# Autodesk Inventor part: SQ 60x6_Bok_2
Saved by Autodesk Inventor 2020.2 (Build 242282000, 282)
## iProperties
Created: 2006-08
Part Number: SQ 60x6_Bok_2
Material: Ogólny
Document SubType Name: Modeling
Designer: F.Stasiak
Manufacturer: Standard
Standards Organization: Custom
Stock Number: DIN EN 10210-2 SQ 60x6
Density: 1 g/cm^3
Appearance: Domyślna
Manager: www.cadconsulting.pl
Company: Fabian Stasiak CAD Consulting
G_L: 500,0 mm
G_W: 60,000 mm
G_H: 60,000 mm
AFG_Item: 60 x 60 x 6
Author: F.Stasiak
Subject: Zbiór ćwiczeń. Autodesk Inventor 2020. Kurs podstawowy
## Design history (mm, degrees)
sketch "AFG_Detailed"
  geometry: L1 (48, -6)-(12, -6); L2 (6, -12)-(6, -48); L3 (12, -54)-(48, -54); L4 (54, -48)-(54, -12); L5 (48, 0)-(12, 0); L6 (0, -12)-(0, -48); L7 (12, -60)-(48, -60); L8 (60, -48)-(60, -12); A1 r 6 centre (48, -12) between (54, -12) and (48, -6); A2 r 12 centre (48, -12) between (60, -12) and (48, 0); A3 r 6 centre (48, -48) between (48, -54) and (54, -48); A4 r 12 centre (48, -48) between (48, -60) and (60, -48); A5 r 12 centre (12, -48) between (0, -48) and (12, -60); A6 r 6 centre (12, -48) between (6, -48) and (12, -54); A7 r 6 centre (12, -12) between (12, -6) and (6, -12); A8 r 12 centre (12, -12) between (12, 0) and (0, -12); 4 further points
  constraints: 16 end point, 16 point on circle, 16 tangent, 8 centre point, 6 point on line, 4 parallel, 2 perpendicular, 1 vertical
  dimensions: "d15" = 60 distance of point (0, -60) point (60, -60) (= GEO_B); "d16" = 6 distance between parallel lines of L7 L3 (= GEO_S); "d17" = 6 distance between parallel lines of L8 L4 (= GEO_S); "d18" = 6 distance between parallel lines of L5 L1 (= GEO_S); "d19" = 6 distance between parallel lines of L6 L2 (= GEO_S); "d20" = 30 distance from line of point (30, -30) L7 (= 0.5 x GEO_H); "d30" = 6 radius of A1 (= GEO_R1 - GEO_S); "GEO_R1" = 12 radius of A2; "d32" = 6 radius of A3 (= GEO_R1 - GEO_S); "d33" = 12 radius of A4 (= GEO_R1); "d34" = 12 radius of A5 (= GEO_R1); "d35" = 6 radius of A6 (= GEO_R1 - GEO_S); "d36" = 6 radius of A7 (= GEO_R1 - GEO_S); "d37" = 12 radius of A8 (= GEO_R1); "d38" = 30 distance from line of L6 point (30, -30) (= 0.5 x GEO_B); "d39" = 60 distance between parallel lines of L7 L5 (= GEO_H)
sketch "AFG_Medium"
  geometry: L1 (54, -6)-(6, -6); L2 (6, -6)-(6, -54); L3 (6, -54)-(54, -54); L4 (54, -54)-(54, -6); L5 (60, 0)-(0, 0); L6 (0, 0)-(0, -60); L7 (0, -60)-(60, -60); L8 (60, -60)-(60, 0); 1 further point
  constraints: 16 end point, 4 parallel, 2 perpendicular, 1 vertical
  dimensions: "GEO_B" = 60 distance of L6.end L7.end; "GEO_S" = 6 distance between parallel lines of L7 L3; "d5" = 6 distance between parallel lines of L8 L4 (= GEO_S); "d6" = 6 distance between parallel lines of L5 L1 (= GEO_S); "d7" = 6 distance between parallel lines of L6 L2 (= GEO_S); "d12" = 30 distance from line of point (30, -30) L7 (= 0.5 x GEO_H); "d40" = 60 distance between parallel lines of L7 L5 (= GEO_H); "d41" = 30 distance from line of L6 point (30, -30) (= 0.5 x GEO_B)
sketch "AFG_Simplified"
  geometry: L1 (60, 0)-(0, 0); L2 (0, 0)-(0, -60); L3 (0, -60)-(60, -60); L4 (60, -60)-(60, 0); 1 further point
  constraints: 8 end point, 2 parallel, 1 perpendicular, 1 vertical
  dimensions: "d23" = 60 distance of L2.end L3.end (= GEO_B); "d28" = 30 distance from line of point (30, -30) L3 (= 0.5 x GEO_H); "d42" = 60 distance between parallel lines of L3 L1 (= GEO_H); "d43" = 30 distance from line of point (30, -30) L2 (= 0.5 x GEO_B)
derived "Szkielet podstawy.ipt"
  sketch "Szkic1"
    geometry: L1 (0, 0)-(1500, 0) reference; L2 (1500, 0)-(1500, 1000) reference; L3 (1500, 1000)-(0, 1000) reference; L4 (0, 1000)-(0, 0) reference
  sketch "Szkic2"
    geometry: L1 (0, 1000)-(0, 0) reference; L2 (0, 0)-(1500, 0) reference; L3 (1500, 0)-(1500, 1000) reference; L4 (500, 1000)-(1500, 1000) reference; L5 (1500, 1000)-(1500, 0) reference; L6 (1500, 0)-(500, 0) reference; L7 (500, 0)-(500, 1000) reference; L8 (1500, 1000)-(0, 1000) reference
node "AFG_StartWorkPoint_SQ 60x6_Bok_2"
node "AFG_EndWorkPoint_SQ 60x6_Bok_2"
node "AFG_HelpAxis"
node "AFG_HelpStart"
node "AFG_HelpEnd"
node "AFG_Midplane"
  node "AFG_Startplane"
  node "AFG_EndPlane"
node "AFG_Profile_AxisX_for_External_Matrix"
extrude "AFG_Detailed_SQ 60x6_Bok_2" join sketch "AFG_Detailed" stored distance "d49" = 0.13; taper "d50" = 0 deg
extrude "AFG_Simplified_SQ 60x6_Bok_2" join sketch "AFG_Simplified" stored distance "d51" = 0.13; taper "d52" = 0 deg
node "Bryła1"
node "Korpusy bryłowe"
node "Korpusy powierzchniowe"
other parameters: "GEO_H" = 60, "AFG_Origin_X" = 0 (= 0 x GEO_B) [user parameter], "AFG_Origin_Y" = 0 (= 0 x GEO_H) [user parameter], "AFG_IP_X2" = 0 (= 0 x GEO_B) [user parameter], "AFG_IP_Y4" = 0 (= 0 x GEO_H) [user parameter], "AFG_IP_X6" = 0 (= 0 x GEO_B) [user parameter], "AFG_IP_Y8" = 0 (= 0 x GEO_H) [user parameter], "d47" = 0, "d48" = 0, "G_L" = 500 [user parameter]
